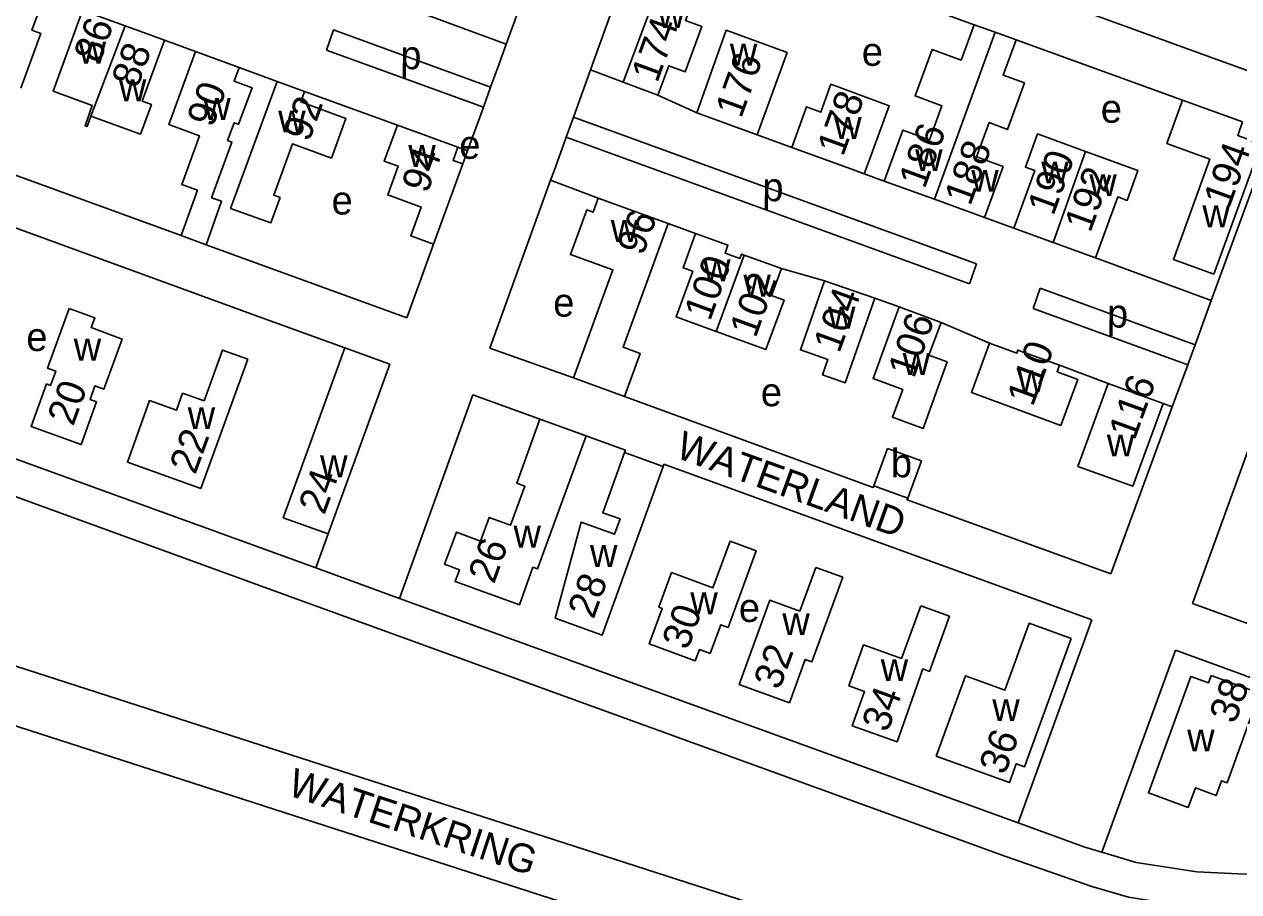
# Model space of a CAD drawing. Extents: x 154320 to 156262, y 382651 to 384180.
# Drawn here: x 155813.5 to 155984.2, y 382833.8 to 382955.7 of the extents above; entities that cross this region are included whole.
import ezdxf

# ---------------------------------------------------------------- set-up
doc = ezdxf.new("R2010")
doc.units = 0
for name, color, linetype in [('BLT_Basislijn', 7, 'Continuous'), ('BLT_Bebouwing', 7, 'Continuous'), ('BLT_Centroide', 7, 'Continuous'), ('BLT_Huisnummer', 7, 'Continuous'), ('BLT_Onderverdeling_panden', 7, 'Continuous'), ('BLT_Straatnaam', 7, 'Continuous')]:
    doc.layers.add(name, color=color, linetype=linetype)

msp = doc.modelspace()

# ---------------------------------------------------------------- linework, layer by layer
at = {"layer": 'BLT_Basislijn'}
for p, q in [((155889.8, 382976.47), (155881.23, 382952.91)), ((155893.06, 382949.27), (155901.37, 382972.26)), ((155946.99, 382955.63), (155901.37, 382972.26)), ((155932.61, 382968.4), (155990.87, 382947.17)), ((155861.67, 382960.11), (155881.23, 382952.91)), ((155879.03, 382946.87), (155856.95, 382954.9)), ((155833.17, 382953.46), (155837.55, 382951.86)), ((155855.94, 382952.07), (155878.01, 382944.05)), ((155881.23, 382952.91), (155880.22, 382950.14)), ((155976.27, 382945.02), (155952.88, 382953.5)), ((155879.03, 382946.87), (155880.22, 382950.14)), ((155892.36, 382947.34), (155893.06, 382949.27)), ((155897.67, 382947.56), (155893.06, 382949.27)), ((155879.03, 382946.87), (155878.01, 382944.05)), ((155892.36, 382947.34), (155890.66, 382942.64)), ((155780.31, 382946.05), (155835.51, 382926)), ((155852.85, 382946.25), (155865.92, 382941.53)), ((155902.55, 382945.75), (155908.02, 382943.24)), ((155878.01, 382944.05), (155875.78, 382937.92)), ((155889.64, 382939.82), (155890.66, 382942.64)), ((155947.32, 382922.04), (155890.66, 382942.64)), ((155916.47, 382940.14), (155921.36, 382938.38)), ((155847.01, 382914.39), (155778.11, 382939.46)), ((155874.44, 382938.43), (155875.78, 382937.92)), ((155889.64, 382939.82), (155887.94, 382935.11)), ((155889.64, 382939.82), (155946.33, 382919.2)), ((155875.78, 382937.92), (155875.1, 382936.06)), ((155988, 382937.76), (155980.32, 382916.85)), ((155887.45, 382933.76), (155887.94, 382935.11)), ((155878.93, 382910.19), (155887.45, 382933.76)), ((155894.14, 382931.23), (155887.45, 382933.76)), ((155931.54, 382934.68), (155934.36, 382933.66)), ((155948.45, 382928.54), (155952.55, 382927.03)), ((155907.82, 382926.29), (155903.97, 382927.68)), ((155839.05, 382924.69), (155867.24, 382914.44)), ((155871.01, 382924.8), (155867.24, 382914.44)), ((155964.05, 382922.85), (155980.32, 382916.85)), ((155925.96, 382919.63), (155919.9, 382921.37)), ((155947.32, 382922.04), (155946.33, 382919.2)), ((155978.05, 382910.66), (155956.26, 382918.58)), ((155936.45, 382915.97), (155933.01, 382917.18)), ((155980.32, 382916.85), (155978.05, 382910.66)), ((155858.54, 382910.2), (155847.01, 382914.39)), ((155955.26, 382915.75), (155977.01, 382907.84)), ((155949.14, 382910.87), (155942.33, 382913.78)), ((155878.93, 382910.19), (155890.69, 382905.98)), ((155978.05, 382910.66), (155977.01, 382907.84)), ((155965.82, 382905.2), (155958.97, 382907.76)), ((155977.01, 382907.84), (155974.84, 382901.94)), ((155765.95, 382906.1), (155852.75, 382874.58)), ((155866.21, 382875.01), (155876.55, 382903.61)), ((155973.53, 382902.41), (155974.84, 382901.94)), ((155974.84, 382901.94), (155966.21, 382878.46)), ((155977.67, 382874.29), (155986.73, 382899.2)), ((155856.19, 382884.09), (155854.46, 382879.28)), ((155852.75, 382874.58), (155864.5, 382870.31)), ((155963.53, 382871.98), (155953.15, 382843.44)), ((155864.5, 382870.31), (155951.44, 382838.74)), ((155964.95, 382839.32), (155975.28, 382867.71)), ((155951.44, 382838.74), (155963.55, 382834.52))]:
    msp.add_line(p, q, dxfattribs=at)
for points in [[(155856.95, 382954.9), (155855.94, 382952.07)], [(155843.67, 382949.63), (155843.67, 382949.63), (155849.02, 382947.66)], [(155632.33, 382923.49), (155936.55, 382825.44)], [(155956.26, 382918.58), (155955.26, 382915.75)], [(155767.66, 382910.8), (155854.46, 382879.28)], [(155657.74, 382906.9), (155933.28, 382818.09), (155939.34, 382814.58), (155944.23, 382809.86), (155948.06, 382804.8), (155950.79, 382799.64), (155952.77, 382794.44), (155952.85, 382794.13)], [(155897.86, 382895.51), (155897.97, 382895.82), (155876.55, 382903.61)], [(155897.83, 382903.4), (155932.8, 382890.6), (155932.89, 382890.84)], [(155963.53, 382871.98), (155903.39, 382893.85), (155903.28, 382893.55)], [(155937.65, 382889.08), (155937.57, 382888.87), (155966.21, 382878.46)], [(155854.46, 382879.28), (155866.21, 382875.01)], [(155964.95, 382839.32), (155969.76, 382837.91), (155978.27, 382836.56), (155985.09, 382836.25), (155990.76, 382836.54), (155996.63, 382837.31), (156001.18, 382838.32), (156005.94, 382839.67), (156012.04, 382841.94), (156019.54, 382845.77), (156024.51, 382848.82), (156029.52, 382852.44), (156033.51, 382855.91), (156037.46, 382859.97), (156040.96, 382864.1), (156044.2, 382868.68), (156049.15, 382876.5)], [(155866.21, 382875.01), (155953.15, 382843.44)], [(155963.55, 382834.52), (155968.66, 382833.02), (155977.76, 382831.58), (155985.11, 382831.25), (155991.21, 382831.55), (155997.5, 382832.38), (156002.4, 382833.47), (156007.5, 382834.91), (156014.06, 382837.36), (156021.99, 382841.41), (156027.28, 382844.66), (156032.64, 382848.52), (156036.94, 382852.27), (156041.17, 382856.61), (156044.91, 382861.04), (156048.35, 382865.9), (156053.37, 382873.82)], [(155977.67, 382874.29), (156017.14, 382859.94), (156014.75, 382853.36), (155975.28, 382867.71)], [(155953.15, 382843.44), (155962.55, 382840.02), (155964.95, 382839.32)]]:
    msp.add_lwpolyline(points, dxfattribs=at)
at = {"layer": 'BLT_Bebouwing'}
for p, q in [((155946.99, 382955.63), (155949.92, 382954.57)), ((155949.92, 382954.57), (155952.88, 382953.5)), ((155984.72, 382941.96), (155976.27, 382945.02)), ((155916.47, 382940.14), (155908.02, 382943.24)), ((155871.01, 382924.8), (155875.1, 382936.06)), ((155839.05, 382924.69), (155835.51, 382926)), ((155933.01, 382917.18), (155925.96, 382919.63)), ((155858.54, 382910.2), (155864.85, 382907.93)), ((155864.85, 382907.93), (155856.19, 382884.09)), ((155890.69, 382905.98), (155897.83, 382903.4)), ((155885.94, 382900.21), (155892.44, 382897.83)), ((155897.86, 382895.51), (155903.28, 382893.55)), ((155937.65, 382889.08), (155932.89, 382890.84))]:
    msp.add_line(p, q, dxfattribs=at)
for points in [[(155902.55, 382945.75), (155904.08, 382949.87), (155906.38, 382949.01), (155908.73, 382955.38), (155906.4, 382956.2), (155908.29, 382961.2), (155903.41, 382963), (155897.67, 382947.56)], [(155816.27, 382959.55), (155814.55, 382954.88), (155815.83, 382954.41), (155813, 382946.72)], [(155822.86, 382942.78), (155822.31, 382941.32), (155822.02, 382941.43), (155823.03, 382944.26), (155817.52, 382946.27), (155821.65, 382957.62)], [(155821.65, 382957.62), (155827.65, 382955.46)], [(155827.65, 382955.46), (155833.17, 382953.46)], [(155934.36, 382933.66), (155936.94, 382940.81), (155940.7, 382939.43), (155942.45, 382944.23), (155938.69, 382945.61), (155941.08, 382952.15), (155945.18, 382950.66), (155946.99, 382955.63)], [(155908.02, 382943.24), (155912.15, 382954.86), (155920.69, 382951.7), (155916.47, 382940.14)], [(155833.17, 382953.46), (155830.06, 382944.88), (155831.35, 382944.41), (155829.84, 382940.25), (155822.86, 382942.78)], [(155837.18, 382950.85), (155837.55, 382951.86)], [(155837.55, 382951.86), (155843.67, 382949.63)], [(155952.88, 382953.5), (155951.08, 382948.53), (155954.05, 382947.44), (155951.66, 382940.89), (155949.1, 382941.87), (155947.31, 382937.08), (155951.05, 382935.68), (155948.45, 382928.54)], [(155835.51, 382926), (155837.82, 382932.36), (155835.61, 382933.15), (155838.11, 382940.03), (155835.05, 382941.14), (155833.82, 382941.59), (155837.18, 382950.85)], [(155843.67, 382949.63), (155842.96, 382947.68), (155845.51, 382946.76), (155843.6, 382941.64), (155842.99, 382941.86), (155842.06, 382939.36), (155842.67, 382939.13), (155839.8, 382931.32), (155841.21, 382930.82), (155839.05, 382924.69)], [(155852.85, 382946.25), (155852.33, 382944.77), (155858.68, 382942.46), (155856.66, 382936.89), (155851.2, 382938.89), (155848.55, 382931.66), (155849.44, 382931.33), (155848.14, 382927.79), (155842.49, 382929.78), (155849.02, 382947.66)], [(155849.02, 382947.66), (155852.85, 382946.25)], [(155897.67, 382947.56), (155902.55, 382945.75)], [(155931.54, 382934.68), (155932.22, 382936.56), (155935.06, 382944.25), (155926.86, 382947.25), (155925.44, 382943.33), (155923.41, 382944.07), (155921.36, 382938.38)], [(155976.27, 382945.02), (155974.07, 382938.92), (155980.11, 382936.72), (155974.99, 382922.61), (155980.67, 382920.55)], [(155984.72, 382941.96), (155984.03, 382940.04), (155987.33, 382938.84), (155980.67, 382920.55)], [(155865.92, 382941.53), (155864.07, 382936.45), (155866.05, 382935.73), (155864.58, 382931.7), (155869.28, 382929.99), (155867.81, 382925.96), (155871.01, 382924.8)], [(155874.44, 382938.43), (155865.92, 382941.53)], [(155962.65, 382937.8), (155955.9, 382940.27), (155954.2, 382935.62), (155955.51, 382935.15), (155952.55, 382927.03)], [(155875.1, 382936.06), (155873.76, 382936.55), (155874.44, 382938.43)], [(155921.36, 382938.38), (155929.66, 382935.36), (155931.54, 382934.68)], [(155964.05, 382922.85), (155967.18, 382931.42), (155968.48, 382930.94), (155970, 382935.12), (155962.65, 382937.8)], [(155941.4, 382931.1), (155934.36, 382933.66)], [(155890.69, 382905.98), (155896.22, 382921.16), (155890.24, 382923.34), (155892.54, 382929.61), (155893.43, 382929.28), (155894.14, 382931.23)], [(155894.14, 382931.23), (155903.97, 382927.68)], [(155948.45, 382928.54), (155941.4, 382931.1)], [(155903.97, 382927.68), (155897.65, 382910.32), (155900.03, 382909.44), (155897.83, 382903.4)], [(155907.82, 382926.29), (155906.07, 382921.48), (155907.43, 382920.99), (155905.1, 382914.58), (155910.73, 382912.53)], [(155914.65, 382923.26), (155914.29, 382923.39), (155914.07, 382922.79), (155911.97, 382923.51), (155912.38, 382924.66), (155907.82, 382926.29)], [(155952.55, 382927.03), (155958.08, 382925.02)], [(155958.08, 382925.02), (155964.05, 382922.85)], [(155914.65, 382923.26), (155919.9, 382921.37)], [(155919.9, 382921.37), (155918.51, 382917.57), (155920.27, 382916.93), (155917.72, 382909.98), (155910.73, 382912.53)], [(155925.96, 382919.63), (155922.58, 382909.93), (155926.43, 382908.59), (155925.68, 382906.42), (155928.88, 382905.31), (155933.01, 382917.18)], [(155942.33, 382913.78), (155940.63, 382909.21), (155943.19, 382908.25), (155939.8, 382898.88), (155935.52, 382900.47), (155936.94, 382904.36), (155932.78, 382905.89), (155936.45, 382915.97)], [(155936.45, 382915.97), (155942.33, 382913.78)], [(155835.72, 382903.86), (155838.75, 382902.77), (155841.33, 382909.91), (155844.91, 382908.62)], [(155856.19, 382884.09), (155849.88, 382886.35), (155858.54, 382910.2)], [(155949.14, 382910.87), (155946.6, 382903.94), (155959.18, 382899.32), (155961.55, 382905.78), (155958.64, 382906.85), (155958.97, 382907.76)], [(155958.97, 382907.76), (155953.14, 382909.9), (155952.98, 382909.46), (155949.14, 382910.87)], [(155844.91, 382908.62), (155838.3, 382890.46), (155827.97, 382894.14), (155831.06, 382902.8), (155834.86, 382901.44), (155835.72, 382903.86)], [(155965.82, 382905.2), (155961.57, 382893.56), (155969.31, 382890.76), (155973.53, 382902.41)], [(155973.53, 382902.41), (155965.82, 382905.2)], [(155892.44, 382897.83), (155885.61, 382879.14), (155884.97, 382879.38), (155883.08, 382874.12), (155874.03, 382877.39), (155874.63, 382879.03), (155872.56, 382879.8), (155874.22, 382884.32), (155877.62, 382883.07), (155878.84, 382886.39), (155881.84, 382885.3), (155883.84, 382890.79), (155882.69, 382891.21), (155885.94, 382900.21)], [(155932.89, 382890.84), (155934.81, 382896.06), (155939.57, 382894.32), (155937.65, 382889.08)], [(155903.28, 382893.55), (155894.72, 382869.84), (155888.1, 382872.22), (155891.73, 382885.74), (155896.44, 382884.03), (155897.22, 382886.17), (155894.78, 382887.05), (155897.86, 382895.51)], [(155909.88, 382867.26), (155908.37, 382867.81), (155907.79, 382866.23), (155901.33, 382868.6), (155903.16, 382873.57), (155902.67, 382873.75), (155904.45, 382878.63), (155910.28, 382876.47), (155912.7, 382883.06)], [(155912.7, 382883.06), (155916.37, 382881.71), (155912.41, 382870.92), (155911.37, 382871.3), (155909.88, 382867.26)]]:
    msp.add_lwpolyline(points, dxfattribs=at)
for points in [[(155819.79, 382915.74), (155823.38, 382914.44), (155822.88, 382913.06), (155827.24, 382911.45), (155824.67, 382904.43), (155823.42, 382904.88), (155822.73, 382902.97), (155823.64, 382902.62), (155821.46, 382896.63), (155814.45, 382899.18), (155816.62, 382905.14), (155817.18, 382904.93), (155817.9, 382906.94), (155816.76, 382907.36)], [(155924.72, 382879.34), (155928.51, 382877.97), (155924.18, 382866.08), (155923.24, 382866.42), (155921.02, 382860.34), (155913.97, 382862.91), (155918.28, 382874.74), (155922.5, 382873.23)], [(155939.47, 382873.94), (155943.51, 382872.49), (155940.73, 382864.74), (155939.76, 382865.09), (155936.15, 382854.86), (155929.86, 382857.11), (155931.56, 382861.93), (155929.39, 382862.7), (155931.43, 382868.46), (155936.79, 382866.56)], [(155941.67, 382852.83), (155945.77, 382864.1), (155951.3, 382862.13), (155954.73, 382871.51), (155960.62, 382869.36), (155954.07, 382851.35), (155952.9, 382851.77), (155951.94, 382849.12)], [(155980.3, 382864.16), (155987.09, 382861.7), (155982.54, 382849.09), (155981.77, 382849.37), (155981.02, 382847.32), (155978.09, 382848.39), (155977.07, 382845.62), (155971.49, 382847.66), (155977.46, 382864.04), (155979.92, 382863.14)]]:
    msp.add_lwpolyline(points, close=True, dxfattribs=at)
at = {"layer": 'BLT_Onderverdeling_panden'}
for p, q in [((155827.65, 382955.46), (155822.86, 382942.78)), ((155949.92, 382954.57), (155941.4, 382931.1)), ((155962.65, 382937.8), (155958.08, 382925.02)), ((155914.65, 382923.26), (155910.73, 382912.53))]:
    msp.add_line(p, q, dxfattribs=at)

# ---------------------------------------------------------------- texts
at = {"layer": 'BLT_Centroide'}
for s, p in [('w', (155902.5, 382955.17)), ('w', (155821.12, 382950.16)), ('w', (155912.65, 382949.89)), ('w', (155826.77, 382944.88)), ('w', (155838.63, 382942.25)), ('w', (155849.16, 382940.5)), ('w', (155927.31, 382939.58)), ('w', (155867.45, 382935.65)), ('w', (155938.7, 382935.05)), ('w', (155946.57, 382932.16)), ('w', (155956.41, 382933.33)), ('w', (155963.17, 382931.54)), ('w', (155979.07, 382927.15)), ('w', (155895.9, 382925.11)), ('w', (155908.89, 382919.58)), ('w', (155914.55, 382917.42)), ('w', (155926.44, 382912.93)), ('w', (155820.43, 382908.43)), ('w', (155936.94, 382906.41)), ('w', (155953.1, 382903.97)), ('w', (155836.45, 382898.8)), ('w', (155965.63, 382894.95)), ('b', (155935.29, 382892.03)), ('w', (155855.06, 382892.03)), ('w', (155882.24, 382882.15)), ('w', (155892.99, 382879.42)), ('w', (155907.09, 382872.77)), ('w', (155920.02, 382869.84)), ('w', (155933.85, 382863.39)), ('w', (155949.53, 382857.77)), ('w', (155976.92, 382853.49))]:
    msp.add_text(s, height=4, dxfattribs=at).set_placement(p)
for s, p in [('p', (155866.32, 382949.39)), ('e', (155931.18, 382949.86)), ('e', (155964.77, 382941.86)), ('e', (155874.6, 382936.79)), ('p', (155917.2, 382930.84)), ('e', (155856.66, 382928.97)), ('e', (155887.81, 382914.61)), ('p', (155965.64, 382913.08)), ('e', (155813.76, 382909.78)), ('e', (155916.99, 382902.02)), ('e', (155913.9, 382871.71))]:
    msp.add_text(s, height=4, rotation=359.5, dxfattribs=at).set_placement(p)
at = {"layer": 'BLT_Huisnummer'}
for s, rotation, p in [('86', 70.0179, (155824.07, 382950.07)), ('174', 70.0179, (155902.44, 382947.32)), ('88', 70.0179, (155829.38, 382946.54)), ('176', 70.0179, (155914.24, 382942.34)), ('90', 70.0179, (155839.97, 382941.06)), ('92', 70.0179, (155853.51, 382939.02)), ('178', 70.0179, (155928.56, 382936.98)), ('186', 70.0179, (155940.03, 382932.43)), ('188', 70.0179, (155946.44, 382930.03)), ('194', 70.0179, (155982.86, 382929.75)), ('94', 70.0179, (155870.15, 382931.79)), ('190', 70.0179, (155958.12, 382928.64)), ('192', 70.0179, (155963.32, 382926.28)), ('96', 70.0179, (155900.44, 382923.04)), ('100', 70.0179, (155909.86, 382913.84)), ('102', 70.0179, (155916.26, 382911.47)), ('104', 70.0179, (155928.03, 382909.34)), ('106', 71.0179, (155938.54, 382905.79)), ('110', 70.0179, (155955.23, 382901.83)), ('116', 70.0179, (155969.53, 382897.08)), ('20', 70.0174, (155820.36, 382899.09)), ('22', 70.0174, (155837.53, 382892.28)), ('24', 70.0189, (155855.66, 382886.61)), ('26', 70.0189, (155879.5, 382876.91)), ('28', 70.0189, (155893.5, 382871.98)), ('30', 70.0188, (155906.75, 382867.62)), ('32', 70.019, (155919.64, 382862.02)), ('38', 70.0118, (155983.66, 382857.24)), ('34', 70.0183, (155934.83, 382856.04)), ('36', 70.0197, (155951.31, 382850.06))]:
    msp.add_text(s, height=4, rotation=rotation, dxfattribs=at).set_placement(p)
at = {"layer": 'BLT_Straatnaam'}
for s, rotation, p in [('WATERLAND', 340.1818, (155904.83, 382894.86)), ('WATERKRING', 341.6818, (155850.31, 382847.41))]:
    msp.add_text(s, height=4, rotation=rotation, dxfattribs=at).set_placement(p)

doc.saveas('drawing.dxf')
